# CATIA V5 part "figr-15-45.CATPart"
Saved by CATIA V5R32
Part number: Part1
Bounding box of the stored display mesh (mm): x 2.5 to 37.676, y -21.475 to 20.775, z 0 to 35.904
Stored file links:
  D:\PROJECTS\Project 2022\CATIA V5 6R 2022\Resources\Part Files\c15_catia_v5_6r2022_prt\figr-15-45.CATPart
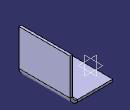
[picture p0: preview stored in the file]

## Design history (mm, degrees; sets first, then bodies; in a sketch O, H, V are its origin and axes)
SheetMetalParameters1: Thickness 2, BendRadius 4, KFactor 0.400515 {= log(min(100,max(20*SheetMetalParameters1.BendRadius,SheetMetalParameters1.Thickness)/SheetMetalParameters1.Thickness))/log(100)/2}, ReliefRadialLength 1, ReliefAxialLength 2, MinimumBendRadius 0
Body1 (main body)
  Sketch1 on xy-plane, origin (0, 0, 0), H (1, 0, 0), V (0, 1, 0)
    line L1 (2.4998, 20.7748) -> (69.1212, 20.7748)
    line L2 (69.1212, 20.7748) -> (69.1212, -21.4753)
    line L3 (69.1212, -21.4753) -> (2.4998, -21.4753)
    line L4 (2.4998, -21.4753) -> (2.4998, 20.7748)
    horizontal: L1 H, L3 H
    vertical: L2 V, L4 V
  Wall1: Thickness 2, Profile Sketch1, OffsetValue 0
  Sketch2 on face of Wall1, origin (0, 0, 2), H (1, 0, 0), V (0, 1, 0)
    line L1 (35.4466, 20.5889) -> (35.4466, -21.306)
    vertical: L1 V
  FlatBend1: Angle 90, Axis Sketch2, FixedPoint vertex [face of Wall1 | face of Wall1 | face of Wall1], KFactor 0.400515 {= log(min(100,max(20*FlatBend1.FlatBendRadius,SheetMetalParameters1.Thickness)/SheetMetalParameters1.Thickness))/log(100)/2}, Radius 4 {= SheetMetalParameters1.BendRadius}
  Unfold1: FoldUnfold_Angles 90, FoldUnfold_FoldUnfoldFaces face of FlatBend1, FoldUnfold_ReferenceFaces face of Wall1
  Fold1: FoldUnfold_Angles 90, FoldUnfold_FoldUnfoldFaces face of FlatBend1, FoldUnfold_ReferenceFaces face of Wall1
